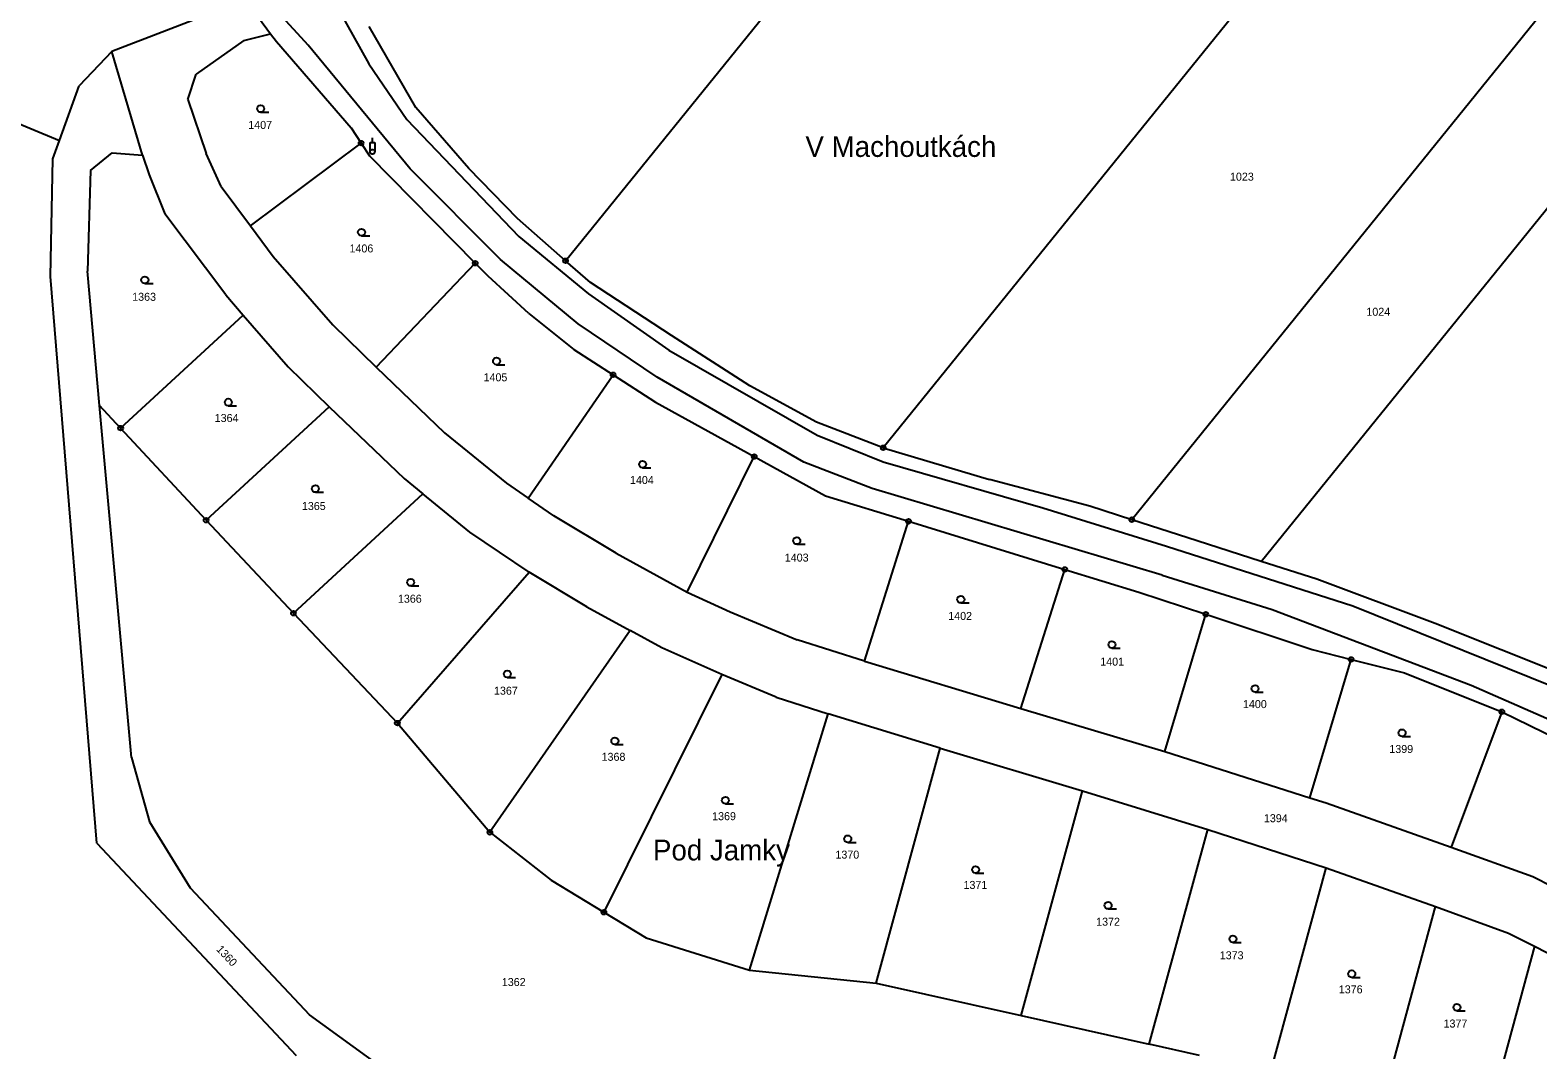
# Model space of a CAD drawing. Extents: x -796130 to -793145, y -1109506 to -1106267.
# Drawn here: x -795165.2 to -794845, y -1107587.8 to -1107371.1 of the extents above; entities that cross this region are included whole.
import ezdxf

# ---------------------------------------------------------------- set-up
doc = ezdxf.new("R2010")
doc.units = 0
for name, color, linetype in [('Vrstva 1', 7, 'Continuous'), ('Vrstva 14', 7, 'Continuous'), ('Vrstva 2', 7, 'Continuous'), ('Vrstva 23', 7, 'Continuous'), ('Vrstva 26', 7, 'Continuous'), ('Vrstva 28', 7, 'Continuous'), ('Vrstva 39', 7, 'Continuous')]:
    doc.layers.add(name, color=color, linetype=linetype)

msp = doc.modelspace()

# ---------------------------------------------------------------- linework, layer by layer
at = {"layer": 'Vrstva 1'}
for p, q in [((-795051.49, -1107420.11), (-794942.76, -1107285.76)), ((-795308.61, -1107332.64), (-795158.99, -1107394.55)), ((-794882.94, -1107334.95), (-794984.02, -1107459.86)), ((-795120.78, -1107362.9), (-795114.17, -1107371.87)), ((-795123.74, -1107366.33), (-795147.87, -1107375.68)), ((-794843.19, -1107366.37), (-794931.23, -1107475.15)), ((-795119.86, -1107373.34), (-795114.17, -1107371.87)), ((-795114.17, -1107371.87), (-795112.94, -1107373.54)), ((-795083.34, -1107387.53), (-795093.21, -1107370.34)), ((-795147.87, -1107375.68), (-795154.84, -1107382.93)), ((-795141.4, -1107397.71), (-795147.87, -1107375.68)), ((-795119.86, -1107373.34), (-795129.98, -1107380.49)), ((-795112.94, -1107373.54), (-795097.06, -1107391.84)), ((-795131.78, -1107385.85), (-795129.98, -1107380.49)), ((-795158.99, -1107394.55), (-795154.84, -1107382.93)), ((-794903.71, -1107484.02), (-794823.32, -1107384.68)), ((-795131.78, -1107385.85), (-795127.83, -1107397.33)), ((-795072.04, -1107400.49), (-795083.34, -1107387.53)), ((-795160.4, -1107398.49), (-795158.99, -1107394.55)), ((-795097.06, -1107391.84), (-795094.94, -1107395.1)), ((-795152.41, -1107400.96), (-795147.81, -1107397.17)), ((-795147.81, -1107397.17), (-795141.4, -1107397.71)), ((-795141.4, -1107397.71), (-795139.94, -1107401.86)), ((-795124.68, -1107404.37), (-795127.83, -1107397.33)), ((-795118.47, -1107412.68), (-795094.94, -1107395.1)), ((-795094.94, -1107395.1), (-795093.19, -1107397.79)), ((-795093.19, -1107397.79), (-795070.68, -1107420.64)), ((-795160.95, -1107423.49), (-795160.4, -1107398.49)), ((-795152.41, -1107400.96), (-795153.05, -1107422.35)), ((-795061.71, -1107411.16), (-795072.04, -1107400.49)), ((-795139.94, -1107401.86), (-795136.6, -1107410.17)), ((-795124.68, -1107404.37), (-795118.47, -1107412.68)), ((-795123.71, -1107427.39), (-795136.6, -1107410.17)), ((-795118.47, -1107412.68), (-795113.59, -1107419.23)), ((-795051.49, -1107420.11), (-795061.71, -1107411.16)), ((-795113.59, -1107419.23), (-795100.93, -1107433.75)), ((-795046.2, -1107424.75), (-795051.49, -1107420.11)), ((-795151.06, -1107543.92), (-795160.95, -1107423.49)), ((-795150.48, -1107450.89), (-795153.05, -1107422.35)), ((-795091.77, -1107442.77), (-795070.68, -1107420.64)), ((-795067.93, -1107423.43), (-795070.68, -1107420.64)), ((-795059.3, -1107431.32), (-795067.93, -1107423.43)), ((-795029, -1107435.98), (-795046.2, -1107424.75)), ((-795123.71, -1107427.39), (-795119.98, -1107431.68)), ((-795146.02, -1107455.69), (-795119.98, -1107431.68)), ((-795119.98, -1107431.68), (-795110.43, -1107442.64)), ((-795059.3, -1107431.32), (-795049.72, -1107438.97)), ((-795100.93, -1107433.75), (-795091.77, -1107442.77)), ((-795012.34, -1107446.67), (-795029, -1107435.98)), ((-795049.72, -1107438.97), (-795041.4, -1107444.35)), ((-795110.43, -1107442.64), (-795101.75, -1107451.19)), ((-795091.77, -1107442.77), (-795077.19, -1107456.67)), ((-795059.48, -1107470.55), (-795041.4, -1107444.35)), ((-795041.4, -1107444.35), (-795032.38, -1107450.19)), ((-794998.22, -1107454.42), (-795012.34, -1107446.67)), ((-795143.74, -1107525.73), (-795150.48, -1107450.89)), ((-795146.02, -1107455.69), (-795150.48, -1107450.89)), ((-795127.86, -1107475.26), (-795101.75, -1107451.19)), ((-795101.75, -1107451.19), (-795085.82, -1107466.41)), ((-795032.38, -1107450.19), (-795011.41, -1107461.74)), ((-795127.86, -1107475.26), (-795146.02, -1107455.69)), ((-794984.02, -1107459.86), (-794998.22, -1107454.42)), ((-795077.19, -1107456.67), (-795064.06, -1107467.39)), ((-795025.65, -1107490.54), (-795011.41, -1107461.74)), ((-795011.41, -1107461.74), (-794996.32, -1107470.05)), ((-794984.02, -1107459.86), (-794961.42, -1107466.63)), ((-795085.82, -1107466.41), (-795081.8, -1107469.69)), ((-795064.06, -1107467.39), (-795059.48, -1107470.55)), ((-794940.13, -1107472.28), (-794961.42, -1107466.63)), ((-795109.31, -1107495.05), (-795081.8, -1107469.69)), ((-795071.86, -1107477.8), (-795081.8, -1107469.69)), ((-795053.97, -1107474.35), (-795059.48, -1107470.55)), ((-794996.32, -1107470.05), (-794978.63, -1107475.5)), ((-795040.78, -1107482.26), (-795053.97, -1107474.35)), ((-794931.23, -1107475.15), (-794940.13, -1107472.28)), ((-795127.86, -1107475.26), (-795109.31, -1107495.05)), ((-795059.27, -1107486.33), (-795071.86, -1107477.8)), ((-794988.01, -1107505.2), (-794978.63, -1107475.5)), ((-794978.63, -1107475.5), (-794945.46, -1107485.72)), ((-794917.34, -1107479.64), (-794931.23, -1107475.15)), ((-794903.71, -1107484.02), (-794917.34, -1107479.64)), ((-795040.78, -1107482.26), (-795025.65, -1107490.54)), ((-794891.92, -1107487.8), (-794903.71, -1107484.02)), ((-795087.24, -1107518.39), (-795059.27, -1107486.33)), ((-795047.02, -1107493.68), (-795059.27, -1107486.33)), ((-794954.8, -1107515.3), (-794945.46, -1107485.72)), ((-794945.46, -1107485.72), (-794929.72, -1107490.57)), ((-794866.75, -1107497.21), (-794891.92, -1107487.8)), ((-795025.65, -1107490.54), (-795016.57, -1107494.72)), ((-794929.72, -1107490.57), (-794915.51, -1107495.26)), ((-795047.02, -1107493.68), (-795037.78, -1107498.73)), ((-795109.31, -1107495.05), (-795087.24, -1107518.39)), ((-795016.57, -1107494.72), (-795002.31, -1107500.68)), ((-794924.2, -1107524.42), (-794915.51, -1107495.26)), ((-794915.51, -1107495.26), (-794892.88, -1107502.73)), ((-794838.71, -1107508.42), (-794866.75, -1107497.21)), ((-795037.78, -1107498.73), (-795067.59, -1107541.6)), ((-795031.06, -1107502.41), (-795037.78, -1107498.73)), ((-794988.01, -1107505.2), (-795002.31, -1107500.68)), ((-795018.3, -1107508.09), (-795031.06, -1107502.41)), ((-794892.88, -1107502.73), (-794884.62, -1107504.84)), ((-794988.01, -1107505.2), (-794954.8, -1107515.3)), ((-794893.39, -1107534.25), (-794884.62, -1107504.84)), ((-794884.62, -1107504.84), (-794873.3, -1107507.73)), ((-795018.3, -1107508.09), (-795043.36, -1107558.58)), ((-795006.8, -1107512.9), (-795018.3, -1107508.09)), ((-794873.3, -1107507.73), (-794852.58, -1107515.99)), ((-795006.8, -1107512.9), (-794995.73, -1107516.39)), ((-795012.45, -1107570.9), (-794995.73, -1107516.39)), ((-794971.94, -1107523.72), (-794995.73, -1107516.39)), ((-794954.8, -1107515.3), (-794924.2, -1107524.42)), ((-794852.58, -1107515.99), (-794863.35, -1107544.78)), ((-794852.58, -1107515.99), (-794824.49, -1107529.82)), ((-795087.24, -1107518.39), (-795067.59, -1107541.6)), ((-795143.74, -1107525.73), (-795139.92, -1107539.36)), ((-794985.53, -1107573.67), (-794971.94, -1107523.72)), ((-794971.94, -1107523.72), (-794941.71, -1107532.77)), ((-794924.2, -1107524.42), (-794893.39, -1107534.25)), ((-794954.71, -1107580.56), (-794941.71, -1107532.77)), ((-794941.71, -1107532.77), (-794915.09, -1107540.97)), ((-794893.39, -1107534.25), (-794889.93, -1107535.35)), ((-794889.93, -1107535.35), (-794863.35, -1107544.78)), ((-795139.92, -1107539.36), (-795131.26, -1107553.38)), ((-795067.59, -1107541.6), (-795054.58, -1107551.8)), ((-794927.52, -1107586.64), (-794915.09, -1107540.97)), ((-794915.09, -1107540.97), (-794889.91, -1107549.15)), ((-795151.06, -1107543.92), (-795108.76, -1107589.05)), ((-794863.35, -1107544.78), (-794846, -1107551.02)), ((-795054.58, -1107551.8), (-795043.36, -1107558.58)), ((-794901.69, -1107592.42), (-794889.91, -1107549.15)), ((-794889.91, -1107549.15), (-794866.67, -1107557.39)), ((-794846, -1107551.02), (-794826.51, -1107561)), ((-795131.26, -1107553.38), (-795105.91, -1107580.39)), ((-794877.66, -1107597.79), (-794866.67, -1107557.39)), ((-794866.67, -1107557.39), (-794851.18, -1107563.03)), ((-795043.36, -1107558.58), (-795034.35, -1107564.02)), ((-795034.35, -1107564.02), (-795012.45, -1107570.9)), ((-794851.18, -1107563.03), (-794845.65, -1107565.77)), ((-794845.65, -1107565.77), (-794855.7, -1107602.7)), ((-794845.65, -1107565.77), (-794824.63, -1107576.66)), ((-795012.45, -1107570.9), (-794985.53, -1107573.67)), ((-794985.53, -1107573.67), (-794954.71, -1107580.56)), ((-795087.38, -1107593.83), (-795105.91, -1107580.39)), ((-794954.71, -1107580.56), (-794927.52, -1107586.64)), ((-794916.83, -1107589.03), (-794927.52, -1107586.64))]:
    msp.add_line(p, q, dxfattribs=at)
at = {"layer": 'Vrstva 2'}
for p, q in [((-795120.18, -1107359.02), (-795106.17, -1107374.32)), ((-795099.77, -1107366.7), (-795093.3, -1107378.26)), ((-795084.5, -1107400.59), (-795106.17, -1107374.32)), ((-795093.3, -1107378.26), (-795085.24, -1107390.1)), ((-795085.24, -1107390.1), (-795061.45, -1107414.95)), ((-795065.36, -1107419.85), (-795084.5, -1107400.59)), ((-795061.45, -1107414.95), (-795046.63, -1107427.16)), ((-795048.81, -1107433.51), (-795065.36, -1107419.85)), ((-795046.63, -1107427.16), (-795029.55, -1107439.14)), ((-795032.06, -1107444.83), (-795048.81, -1107433.51)), ((-795029.55, -1107439.14), (-794998.05, -1107457.19)), ((-795000.89, -1107462.96), (-795032.06, -1107444.83)), ((-794998.05, -1107457.19), (-794984.07, -1107462.85)), ((-794986.4, -1107468.53), (-795000.89, -1107462.96)), ((-794984.07, -1107462.85), (-794950.14, -1107472.62)), ((-794924.76, -1107486.94), (-794986.4, -1107468.53)), ((-794950.14, -1107472.62), (-794923.88, -1107480.81)), ((-794923.88, -1107480.81), (-794884.26, -1107493.46)), ((-794924.76, -1107486.94), (-794901.4, -1107494.24)), ((-794901.4, -1107494.24), (-794859.11, -1107510.35)), ((-794884.26, -1107493.46), (-794841.93, -1107510.52)), ((-794859.11, -1107510.35), (-794837.96, -1107519.62))]:
    msp.add_line(p, q, dxfattribs=at)
at = {"layer": 'Vrstva 23'}
for p, q in [((-795116.28, -1107388.57), (-795114.53, -1107388.57)), ((-795094.85, -1107414.82), (-795093.1, -1107414.82)), ((-795140.88, -1107424.96), (-795139.13, -1107424.96)), ((-795066.16, -1107442.21), (-795064.41, -1107442.21)), ((-795123.15, -1107450.93), (-795121.4, -1107450.93)), ((-795035.14, -1107464.13), (-795033.39, -1107464.13)), ((-795104.65, -1107469.33), (-795102.9, -1107469.33)), ((-795002.39, -1107480.38), (-795000.64, -1107480.38)), ((-795084.41, -1107489.24), (-795082.66, -1107489.24)), ((-794967.54, -1107492.85), (-794965.79, -1107492.85)), ((-794935.44, -1107502.48), (-794933.69, -1107502.48)), ((-795063.88, -1107508.69), (-795062.13, -1107508.69)), ((-794905.03, -1107511.83), (-794903.28, -1107511.83)), ((-795041.03, -1107522.94), (-795039.28, -1107522.94)), ((-794873.79, -1107521.22), (-794872.04, -1107521.22)), ((-795017.55, -1107535.56), (-795015.8, -1107535.56)), ((-794991.55, -1107543.74), (-794989.8, -1107543.74)), ((-794964.4, -1107550.28), (-794962.65, -1107550.28)), ((-794936.25, -1107557.89), (-794934.5, -1107557.89)), ((-794909.73, -1107565.02), (-794907.98, -1107565.02)), ((-794884.49, -1107572.43), (-794882.74, -1107572.43)), ((-794862.15, -1107579.54), (-794860.4, -1107579.54))]:
    msp.add_line(p, q, dxfattribs=at)
for centre in [(-795116.28, -1107387.82), (-795094.85, -1107414.07), (-795140.88, -1107424.21), (-795066.16, -1107441.46), (-795123.15, -1107450.18), (-795035.14, -1107463.38), (-795104.65, -1107468.58), (-795002.39, -1107479.63), (-795084.41, -1107488.49), (-794967.54, -1107492.1), (-794935.44, -1107501.73), (-795063.88, -1107507.94), (-794905.03, -1107511.08), (-794873.79, -1107520.47), (-795041.03, -1107522.19), (-795017.55, -1107534.81), (-794991.55, -1107542.99), (-794964.4, -1107549.53), (-794936.25, -1107557.14), (-794909.73, -1107564.27), (-794884.49, -1107571.68), (-794862.15, -1107578.79)]:
    msp.add_circle(centre, 0.75, dxfattribs=at)
at = {"layer": 'Vrstva 26'}
for p, q in [((-795093.03, -1107396.96), (-795093.03, -1107394.96)), ((-795093.03, -1107394.96), (-795092.03, -1107394.96)), ((-795092.53, -1107394.96), (-795092.53, -1107393.96)), ((-795092.03, -1107394.96), (-795092.03, -1107396.96)), ((-795093.03, -1107396.86), (-795092.93, -1107396.66)), ((-795093.03, -1107397.06), (-795093.03, -1107396.86)), ((-795092.93, -1107397.26), (-795093.03, -1107397.06)), ((-795092.93, -1107396.66), (-795092.83, -1107396.56)), ((-795092.83, -1107397.36), (-795092.93, -1107397.26)), ((-795092.83, -1107396.56), (-795092.63, -1107396.46)), ((-795092.63, -1107397.46), (-795092.83, -1107397.36)), ((-795092.63, -1107396.46), (-795092.43, -1107396.46)), ((-795092.43, -1107397.46), (-795092.63, -1107397.46)), ((-795092.53, -1107396.96), (-795092.53, -1107396.96)), ((-795092.43, -1107396.46), (-795092.23, -1107396.56)), ((-795092.23, -1107397.36), (-795092.43, -1107397.46)), ((-795092.23, -1107396.56), (-795092.13, -1107396.66)), ((-795092.13, -1107397.26), (-795092.23, -1107397.36)), ((-795092.13, -1107396.66), (-795092.03, -1107396.86)), ((-795092.03, -1107397.06), (-795092.13, -1107397.26)), ((-795092.03, -1107396.86), (-795092.03, -1107397.06))]:
    msp.add_line(p, q, dxfattribs=at)
at = {"layer": 'Vrstva 28'}
for centre, radius in [((-795094.94, -1107395.1), 0.5), ((-795094.94, -1107395.1), 0.01), ((-795070.68, -1107420.64), 0.5), ((-795051.49, -1107420.11), 0.5), ((-795051.49, -1107420.11), 0.01), ((-795070.68, -1107420.64), 0.01), ((-795041.4, -1107444.35), 0.5), ((-795041.4, -1107444.35), 0.01), ((-795146.02, -1107455.69), 0.5), ((-795146.02, -1107455.69), 0.01), ((-795011.41, -1107461.74), 0.5), ((-795011.41, -1107461.74), 0.01), ((-794984.02, -1107459.86), 0.5), ((-794984.02, -1107459.86), 0.01), ((-795127.86, -1107475.26), 0.5), ((-794978.63, -1107475.5), 0.5), ((-794931.23, -1107475.15), 0.5), ((-795127.86, -1107475.26), 0.01), ((-794978.63, -1107475.5), 0.01), ((-794931.23, -1107475.15), 0.01), ((-794945.46, -1107485.72), 0.5), ((-794945.46, -1107485.72), 0.01), ((-795109.31, -1107495.05), 0.5), ((-795109.31, -1107495.05), 0.01), ((-794915.51, -1107495.26), 0.5), ((-794915.51, -1107495.26), 0.01), ((-794884.62, -1107504.84), 0.5), ((-794884.62, -1107504.84), 0.01), ((-794852.58, -1107515.99), 0.5), ((-794852.58, -1107515.99), 0.01), ((-795087.24, -1107518.39), 0.5), ((-795087.24, -1107518.39), 0.01), ((-795067.59, -1107541.6), 0.5), ((-795067.59, -1107541.6), 0.01), ((-795043.36, -1107558.58), 0.5), ((-795043.36, -1107558.58), 0.01)]:
    msp.add_circle(centre, radius, dxfattribs=at)

# ---------------------------------------------------------------- texts
at = {"layer": 'Vrstva 14'}
for s, p in [('1407', (-795118.911, -1107392.1)), ('1023', (-794910.359, -1107403.1)), ('1406', (-795097.405, -1107418.35)), ('1363', (-795143.57, -1107428.63)), ('1024', (-794881.385, -1107431.81)), ('1405', (-795068.931, -1107445.74)), ('1364', (-795126.046, -1107454.39)), ('1404', (-795037.821, -1107467.57)), ('1365', (-795107.516, -1107473.1)), ('1403', (-795004.935, -1107484.06)), ('1366', (-795087.12, -1107492.8)), ('1402', (-794970.215, -1107496.46)), ('1401', (-794937.918, -1107506.17)), ('1367', (-795066.706, -1107512.35)), ('1400', (-794907.604, -1107515.2)), ('1399', (-794876.51, -1107524.74)), ('1368', (-795043.85, -1107526.4)), ('1369', (-795020.37, -1107539.02)), ('1394', (-794903.156, -1107539.45)), ('1370', (-794994.176, -1107547.19)), ('1371', (-794966.97, -1107553.63)), ('1372', (-794938.796, -1107561.45)), ('1373', (-794912.536, -1107568.58)), ('1362', (-795065.05, -1107574.27)), ('1376', (-794887.246, -1107575.82)), ('1377', (-794864.993, -1107583.09))]:
    msp.add_text(s, height=1.7, dxfattribs=at).set_placement(p)
msp.add_text('1360', height=1.7, rotation=313.2, dxfattribs=at).set_placement((-795125.815, -1107566.574))
at = {"layer": 'Vrstva 39'}
for s, p in [('V Machoutkách', (-795000.55, -1107398.05)), ('Pod Jamky', (-795032.94, -1107547.56))]:
    msp.add_text(s, height=4.4, dxfattribs=at).set_placement(p)

doc.saveas('drawing.dxf')
